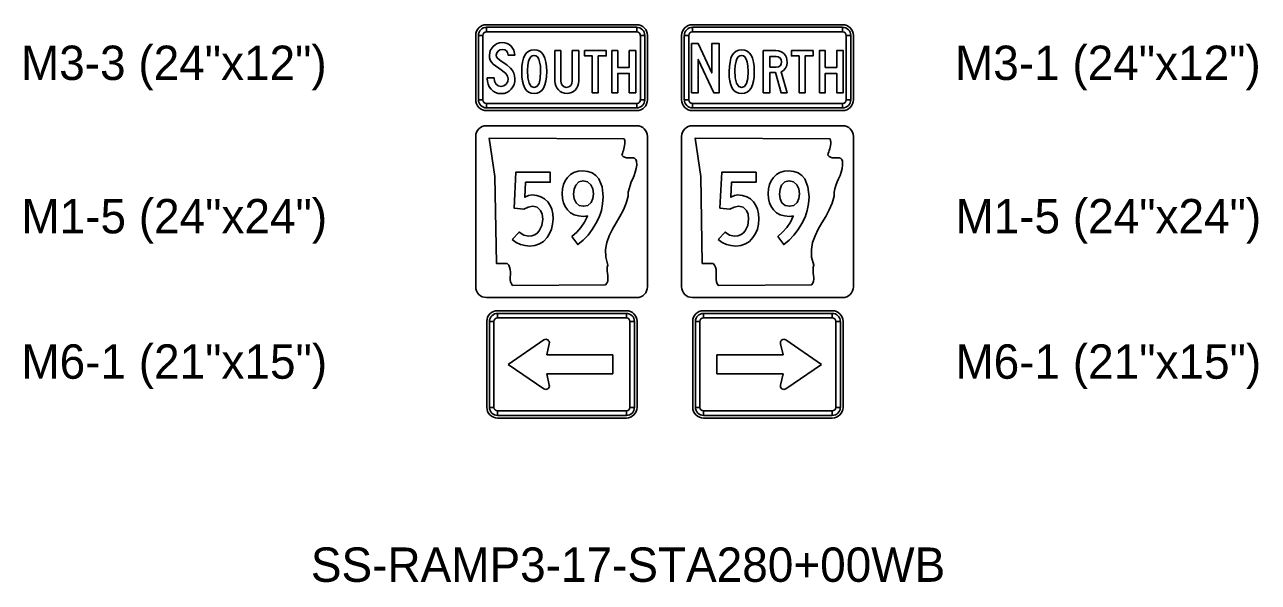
# Model space of a CAD drawing. Extents: x 620856.8 to 620948.6, y 415598.8 to 415658.2.
# Drawn here: x 620932.7 to 620947.07, y 415628.85 to 415635.34 of the extents above; entities that cross this region are included whole.
import ezdxf

# ---------------------------------------------------------------- set-up
doc = ezdxf.new("R2010")
doc.units = 0
doc.layers.add('SIGNS', color=7, linetype='Continuous')

msp = doc.modelspace()

# ---------------------------------------------------------------- linework, layer by layer
at = {"layer": 'SIGNS'}
for p, q in [((620939.83, 415635.34), (620938.08, 415635.34)), ((620938.08, 415635.256), (620938.08, 415635.309)), ((620939.83, 415635.309), (620939.83, 415635.256)), ((620942.228, 415635.34), (620940.478, 415635.34)), ((620940.478, 415635.256), (620940.478, 415635.309)), ((620942.228, 415635.309), (620942.228, 415635.256)), ((620937.955, 415635.215), (620937.955, 415634.465)), ((620937.986, 415635.215), (620938.038, 415635.215)), ((620939.872, 415635.215), (620939.924, 415635.215)), ((620939.955, 415634.465), (620939.955, 415635.215)), ((620940.353, 415635.215), (620940.353, 415634.465)), ((620940.384, 415635.215), (620940.436, 415635.215)), ((620942.27, 415635.215), (620942.322, 415635.215)), ((620942.353, 415634.465), (620942.353, 415635.215)), ((620938.038, 415634.465), (620937.986, 415634.465)), ((620938.08, 415634.371), (620938.08, 415634.423)), ((620939.83, 415634.423), (620939.83, 415634.371)), ((620939.924, 415634.465), (620939.872, 415634.465)), ((620940.436, 415634.465), (620940.384, 415634.465)), ((620940.478, 415634.371), (620940.478, 415634.423)), ((620942.228, 415634.423), (620942.228, 415634.371)), ((620942.322, 415634.465), (620942.27, 415634.465)), ((620938.08, 415634.34), (620939.83, 415634.34)), ((620940.478, 415634.34), (620942.228, 415634.34)), ((620939.83, 415634.164), (620938.08, 415634.164)), ((620942.228, 415634.164), (620940.478, 415634.164)), ((620937.955, 415634.039), (620937.955, 415632.289)), ((620939.955, 415632.289), (620939.955, 415634.039)), ((620940.353, 415634.039), (620940.353, 415632.289)), ((620942.353, 415632.289), (620942.353, 415634.039)), ((620937.955, 415632.289), (620937.955, 415632.289)), ((620940.353, 415632.289), (620940.353, 415632.289)), ((620938.08, 415632.164), (620939.83, 415632.164)), ((620940.478, 415632.164), (620942.228, 415632.164)), ((620938.209, 415632.011), (620939.709, 415632.011)), ((620938.209, 415631.98), (620938.209, 415631.928)), ((620939.709, 415631.928), (620939.709, 415631.98)), ((620942.107, 415632.011), (620940.607, 415632.011)), ((620940.607, 415631.928), (620940.607, 415631.98)), ((620942.107, 415631.98), (620942.107, 415631.928)), ((620938.084, 415630.886), (620938.084, 415631.886)), ((620938.167, 415631.886), (620938.115, 415631.886)), ((620939.803, 415631.886), (620939.751, 415631.886)), ((620939.834, 415631.886), (620939.834, 415630.886)), ((620940.482, 415631.886), (620940.482, 415630.886)), ((620940.513, 415631.886), (620940.565, 415631.886)), ((620942.148, 415631.886), (620942.201, 415631.886)), ((620942.232, 415630.886), (620942.232, 415631.886)), ((620938.334, 415631.386), (620938.749, 415631.672)), ((620938.812, 415631.627), (620938.782, 415631.496)), ((620941.504, 415631.627), (620941.534, 415631.496)), ((620941.982, 415631.386), (620941.567, 415631.672)), ((620938.782, 415631.496), (620939.553, 415631.496)), ((620939.553, 415631.496), (620939.553, 415631.277)), ((620941.534, 415631.496), (620940.763, 415631.496)), ((620940.763, 415631.496), (620940.763, 415631.277)), ((620938.334, 415631.386), (620938.334, 415631.386)), ((620938.749, 415631.101), (620938.334, 415631.386)), ((620939.553, 415631.277), (620938.782, 415631.277)), ((620938.782, 415631.277), (620938.812, 415631.146)), ((620939.553, 415631.277), (620939.553, 415631.277)), ((620940.763, 415631.277), (620940.763, 415631.277)), ((620940.763, 415631.277), (620941.534, 415631.277)), ((620941.534, 415631.277), (620941.504, 415631.146)), ((620941.567, 415631.101), (620941.982, 415631.386)), ((620941.982, 415631.386), (620941.982, 415631.386)), ((620938.115, 415630.886), (620938.167, 415630.886)), ((620938.209, 415630.845), (620938.209, 415630.793)), ((620939.709, 415630.793), (620939.709, 415630.845)), ((620939.751, 415630.886), (620939.803, 415630.886)), ((620940.565, 415630.886), (620940.513, 415630.886)), ((620940.607, 415630.793), (620940.607, 415630.845)), ((620942.107, 415630.845), (620942.107, 415630.793)), ((620942.201, 415630.886), (620942.148, 415630.886)), ((620939.709, 415630.761), (620938.209, 415630.761)), ((620940.607, 415630.761), (620942.107, 415630.761))]:
    msp.add_line(p, q, dxfattribs=at)
for points in [[(620939.83, 415635.309), (620938.08, 415635.309), (620938.08, 415635.256), (620939.83, 415635.256), (620939.83, 415635.309), (620939.83, 415635.309)], [(620942.228, 415635.309), (620940.478, 415635.309), (620940.478, 415635.256), (620942.228, 415635.256), (620942.228, 415635.309), (620942.228, 415635.309)], [(620937.986, 415635.215), (620937.986, 415634.465), (620938.038, 415634.465), (620938.038, 415635.215), (620937.986, 415635.215), (620937.986, 415635.215)], [(620938.089, 415634.72), (620938.089, 415634.715), (620938.091, 415634.68), (620938.099, 415634.648), (620938.113, 415634.618), (620938.133, 415634.591), (620938.158, 415634.567), (620938.186, 415634.55), (620938.216, 415634.54), (620938.251, 415634.537), (620938.285, 415634.54), (620938.316, 415634.55), (620938.343, 415634.566), (620938.368, 415634.589), (620938.387, 415634.616), (620938.401, 415634.645), (620938.409, 415634.677), (620938.412, 415634.712), (620938.408, 415634.745), (620938.399, 415634.776), (620938.383, 415634.806), (620938.36, 415634.834), (620938.317, 415634.871), (620938.251, 415634.917), (620938.207, 415634.95), (620938.197, 415634.967), (620938.194, 415634.986), (620938.199, 415635.011), (620938.215, 415635.033), (620938.237, 415635.047), (620938.263, 415635.052), (620938.292, 415635.048), (620938.312, 415635.034), (620938.324, 415635.015), (620938.332, 415634.986), (620938.412, 415634.986), (620938.399, 415635.044), (620938.368, 415635.09), (620938.346, 415635.108), (620938.321, 415635.121), (620938.292, 415635.129), (620938.261, 415635.131), (620938.232, 415635.129), (620938.205, 415635.12), (620938.18, 415635.107), (620938.158, 415635.087), (620938.125, 415635.039), (620938.115, 415634.984), (620938.117, 415634.955), (620938.125, 415634.928), (620938.139, 415634.904), (620938.158, 415634.882), (620938.251, 415634.816), (620938.286, 415634.789), (620938.307, 415634.77), (620938.326, 415634.741), (620938.333, 415634.711), (620938.327, 415634.677), (620938.311, 415634.648), (620938.284, 415634.627), (620938.251, 415634.62), (620938.215, 415634.628), (620938.188, 415634.651), (620938.172, 415634.683), (620938.168, 415634.72)], [(620939.924, 415634.465), (620939.924, 415635.215), (620939.872, 415635.215), (620939.872, 415634.465), (620939.924, 415634.465), (620939.924, 415634.465)], [(620940.384, 415635.215), (620940.384, 415634.465), (620940.436, 415634.465), (620940.436, 415635.215), (620940.384, 415635.215), (620940.384, 415635.215)], [(620942.322, 415634.465), (620942.322, 415635.215), (620942.27, 415635.215), (620942.27, 415634.465), (620942.322, 415634.465), (620942.322, 415634.465)], [(620938.877, 415635.038), (620938.877, 415634.683), (620938.88, 415634.655), (620938.888, 415634.628), (620938.901, 415634.604), (620938.918, 415634.581), (620938.939, 415634.562), (620938.963, 415634.549), (620938.989, 415634.541), (620939.018, 415634.539), (620939.045, 415634.541), (620939.071, 415634.55), (620939.094, 415634.564), (620939.116, 415634.583), (620939.132, 415634.606), (620939.144, 415634.63), (620939.152, 415634.657), (620939.154, 415634.685), (620939.154, 415635.038), (620939.079, 415635.038), (620939.079, 415634.688), (620939.075, 415634.657), (620939.062, 415634.633), (620939.04, 415634.615), (620939.01, 415634.609), (620938.983, 415634.615), (620938.961, 415634.634), (620938.949, 415634.658), (620938.945, 415634.688), (620938.945, 415635.038)], [(620939.311, 415634.548), (620939.382, 415634.548), (620939.382, 415634.977), (620939.474, 415634.977), (620939.474, 415635.038), (620939.222, 415635.038), (620939.222, 415634.977), (620939.311, 415634.977)], [(620939.541, 415634.548), (620939.609, 415634.548), (620939.609, 415634.773), (620939.743, 415634.773), (620939.743, 415634.548), (620939.818, 415634.548), (620939.818, 415635.038), (620939.743, 415635.038), (620939.743, 415634.842), (620939.609, 415634.842), (620939.609, 415635.038), (620939.541, 415635.038)], [(620940.468, 415634.548), (620940.547, 415634.548), (620940.547, 415634.935), (620940.727, 415634.548), (620940.791, 415634.548), (620940.791, 415635.12), (620940.704, 415635.12), (620940.704, 415634.779), (620940.547, 415635.12), (620940.468, 415635.12)], [(620941.72, 415634.548), (620941.791, 415634.548), (620941.791, 415634.977), (620941.883, 415634.977), (620941.883, 415635.038), (620941.631, 415635.038), (620941.631, 415634.977), (620941.72, 415634.977)], [(620941.958, 415634.548), (620942.025, 415634.548), (620942.025, 415634.773), (620942.159, 415634.773), (620942.159, 415634.548), (620942.234, 415634.548), (620942.234, 415635.038), (620942.159, 415635.038), (620942.159, 415634.842), (620942.025, 415634.842), (620942.025, 415635.038), (620941.958, 415635.038)], [(620938.08, 415634.371), (620939.83, 415634.371), (620939.83, 415634.423), (620938.08, 415634.423), (620938.08, 415634.371), (620938.08, 415634.371)], [(620940.478, 415634.371), (620942.228, 415634.371), (620942.228, 415634.423), (620940.478, 415634.423), (620940.478, 415634.371), (620940.478, 415634.371)], [(620939.685, 415634.01), (620939.69, 415633.991), (620939.691, 415633.971), (620939.691, 415633.952), (620939.688, 415633.933), (620939.684, 415633.914), (620939.679, 415633.895), (620939.674, 415633.876), (620939.668, 415633.858), (620939.663, 415633.839), (620939.658, 415633.821), (620939.672, 415633.805), (620939.689, 415633.796), (620939.709, 415633.792), (620939.73, 415633.791), (620939.752, 415633.792), (620939.772, 415633.792), (620939.791, 415633.79), (620939.808, 415633.784), (620939.821, 415633.772), (620939.829, 415633.752), (620939.83, 415633.706), (620939.824, 415633.664), (620939.813, 415633.623), (620939.799, 415633.585), (620939.783, 415633.546), (620939.767, 415633.509), (620939.752, 415633.47), (620939.74, 415633.43), (620939.732, 415633.389), (620939.73, 415633.345), (620939.708, 415633.263), (620939.674, 415633.185), (620939.633, 415633.109), (620939.589, 415633.034), (620939.546, 415632.959), (620939.508, 415632.883), (620939.48, 415632.805), (620939.466, 415632.722), (620939.469, 415632.635), (620939.495, 415632.541), (620939.487, 415632.518), (620939.485, 415632.494), (620939.485, 415632.47), (620939.488, 415632.446), (620939.492, 415632.422), (620939.494, 415632.399), (620939.495, 415632.376), (620939.492, 415632.354), (620939.483, 415632.333), (620939.468, 415632.313), (620938.384, 415632.303), (620938.37, 415632.323), (620938.361, 415632.347), (620938.357, 415632.373), (620938.357, 415632.401), (620938.358, 415632.431), (620938.358, 415632.461), (620938.356, 415632.49), (620938.35, 415632.516), (620938.339, 415632.541), (620938.321, 415632.561), (620938.195, 415632.561), (620938.177, 415633.573), (620938.113, 415634.02), (620939.685, 415634.01), (620939.685, 415634.01)], [(620942.083, 415634.01), (620942.088, 415633.991), (620942.089, 415633.971), (620942.089, 415633.952), (620942.086, 415633.933), (620942.082, 415633.914), (620942.077, 415633.895), (620942.072, 415633.876), (620942.066, 415633.858), (620942.061, 415633.839), (620942.056, 415633.821), (620942.07, 415633.805), (620942.087, 415633.796), (620942.107, 415633.792), (620942.128, 415633.791), (620942.15, 415633.792), (620942.17, 415633.792), (620942.189, 415633.79), (620942.206, 415633.784), (620942.219, 415633.772), (620942.227, 415633.752), (620942.228, 415633.706), (620942.222, 415633.664), (620942.211, 415633.623), (620942.197, 415633.585), (620942.181, 415633.546), (620942.165, 415633.509), (620942.15, 415633.47), (620942.138, 415633.43), (620942.13, 415633.389), (620942.128, 415633.345), (620942.106, 415633.263), (620942.072, 415633.185), (620942.031, 415633.109), (620941.987, 415633.034), (620941.944, 415632.959), (620941.906, 415632.883), (620941.878, 415632.805), (620941.864, 415632.722), (620941.867, 415632.635), (620941.893, 415632.541), (620941.885, 415632.518), (620941.883, 415632.494), (620941.883, 415632.47), (620941.886, 415632.446), (620941.89, 415632.422), (620941.892, 415632.399), (620941.893, 415632.376), (620941.89, 415632.354), (620941.881, 415632.333), (620941.866, 415632.313), (620940.782, 415632.303), (620940.768, 415632.323), (620940.759, 415632.347), (620940.755, 415632.373), (620940.755, 415632.401), (620940.756, 415632.431), (620940.756, 415632.461), (620940.754, 415632.49), (620940.748, 415632.516), (620940.737, 415632.541), (620940.719, 415632.561), (620940.593, 415632.561), (620940.575, 415633.573), (620940.511, 415634.02), (620942.083, 415634.01), (620942.083, 415634.01)], [(620938.38, 415632.838), (620938.427, 415632.805), (620938.477, 415632.782), (620938.53, 415632.768), (620938.584, 415632.763), (620938.644, 415632.769), (620938.697, 415632.788), (620938.744, 415632.818), (620938.785, 415632.861), (620938.815, 415632.909), (620938.837, 415632.961), (620938.85, 415633.019), (620938.855, 415633.082), (620938.851, 415633.139), (620938.84, 415633.191), (620938.82, 415633.237), (620938.793, 415633.278), (620938.757, 415633.312), (620938.714, 415633.337), (620938.665, 415633.352), (620938.611, 415633.358), (620938.569, 415633.351), (620938.526, 415633.331), (620938.535, 415633.506), (620938.822, 415633.506), (620938.822, 415633.622), (620938.421, 415633.622), (620938.401, 415633.206), (620938.517, 415633.191), (620938.566, 415633.217), (620938.619, 415633.226), (620938.671, 415633.214), (620938.709, 415633.179), (620938.729, 415633.133), (620938.735, 415633.076), (620938.725, 415633.001), (620938.695, 415632.94), (620938.671, 415632.913), (620938.642, 415632.894), (620938.609, 415632.882), (620938.572, 415632.879), (620938.514, 415632.891), (620938.46, 415632.926)], [(620940.778, 415632.838), (620940.825, 415632.805), (620940.875, 415632.782), (620940.928, 415632.768), (620940.982, 415632.763), (620941.042, 415632.769), (620941.095, 415632.788), (620941.142, 415632.818), (620941.183, 415632.861), (620941.213, 415632.909), (620941.235, 415632.961), (620941.248, 415633.019), (620941.253, 415633.082), (620941.249, 415633.139), (620941.238, 415633.191), (620941.218, 415633.237), (620941.191, 415633.278), (620941.155, 415633.312), (620941.112, 415633.337), (620941.063, 415633.352), (620941.009, 415633.358), (620940.967, 415633.351), (620940.924, 415633.331), (620940.933, 415633.506), (620941.22, 415633.506), (620941.22, 415633.622), (620940.819, 415633.622), (620940.799, 415633.206), (620940.915, 415633.191), (620940.964, 415633.217), (620941.017, 415633.226), (620941.069, 415633.214), (620941.107, 415633.179), (620941.127, 415633.133), (620941.133, 415633.076), (620941.123, 415633.001), (620941.093, 415632.94), (620941.069, 415632.913), (620941.04, 415632.894), (620941.007, 415632.882), (620940.97, 415632.879), (620940.912, 415632.891), (620940.858, 415632.926)], [(620938.209, 415631.98), (620939.709, 415631.98), (620939.709, 415631.928), (620938.209, 415631.928), (620938.209, 415631.98), (620938.209, 415631.98)], [(620942.107, 415631.98), (620940.607, 415631.98), (620940.607, 415631.928), (620942.107, 415631.928), (620942.107, 415631.98), (620942.107, 415631.98)], [(620938.115, 415630.886), (620938.115, 415631.886), (620938.167, 415631.886), (620938.167, 415630.886), (620938.115, 415630.886), (620938.115, 415630.886)], [(620939.803, 415631.886), (620939.803, 415630.886), (620939.751, 415630.886), (620939.751, 415631.886), (620939.803, 415631.886), (620939.803, 415631.886)], [(620940.513, 415631.886), (620940.513, 415630.886), (620940.565, 415630.886), (620940.565, 415631.886), (620940.513, 415631.886), (620940.513, 415631.886)], [(620942.201, 415630.886), (620942.201, 415631.886), (620942.148, 415631.886), (620942.148, 415630.886), (620942.201, 415630.886), (620942.201, 415630.886)], [(620939.709, 415630.793), (620938.209, 415630.793), (620938.209, 415630.845), (620939.709, 415630.845), (620939.709, 415630.793), (620939.709, 415630.793)], [(620940.607, 415630.793), (620942.107, 415630.793), (620942.107, 415630.845), (620940.607, 415630.845), (620940.607, 415630.793), (620940.607, 415630.793)]]:
    msp.add_lwpolyline(points, close=True, dxfattribs=at)
for points in [[(620938.782, 415634.794), (620938.779, 415634.853), (620938.773, 415634.905), (620938.761, 415634.949), (620938.746, 415634.985), (620938.725, 415635.012), (620938.7, 415635.032), (620938.671, 415635.044), (620938.637, 415635.048), (620938.602, 415635.044), (620938.573, 415635.032), (620938.547, 415635.012), (620938.527, 415634.985), (620938.511, 415634.949), (620938.499, 415634.905), (620938.492, 415634.853), (620938.49, 415634.794), (620938.492, 415634.734), (620938.499, 415634.682), (620938.51, 415634.638), (620938.526, 415634.602), (620938.546, 415634.574), (620938.571, 415634.554), (620938.6, 415634.542), (620938.634, 415634.539), (620938.669, 415634.542), (620938.699, 415634.554), (620938.724, 415634.574), (620938.745, 415634.602), (620938.761, 415634.638), (620938.772, 415634.682), (620938.779, 415634.734), (620938.782, 415634.794)], [(620938.711, 415634.796), (620938.706, 415634.715), (620938.692, 415634.656), (620938.668, 415634.621), (620938.635, 415634.61), (620938.601, 415634.622), (620938.577, 415634.659), (620938.562, 415634.721), (620938.557, 415634.809), (620938.56, 415634.866), (620938.57, 415634.915), (620938.581, 415634.944), (620938.595, 415634.965), (620938.613, 415634.978), (620938.635, 415634.982), (620938.656, 415634.978), (620938.674, 415634.964), (620938.688, 415634.94), (620938.699, 415634.908), (620938.708, 415634.857), (620938.711, 415634.796)], [(620941.198, 415634.794), (620941.196, 415634.853), (620941.189, 415634.905), (620941.178, 415634.949), (620941.162, 415634.985), (620941.141, 415635.012), (620941.117, 415635.032), (620941.087, 415635.044), (620941.053, 415635.048), (620941.019, 415635.044), (620940.989, 415635.032), (620940.964, 415635.012), (620940.943, 415634.985), (620940.927, 415634.949), (620940.916, 415634.905), (620940.909, 415634.853), (620940.906, 415634.794), (620940.908, 415634.734), (620940.915, 415634.682), (620940.926, 415634.638), (620940.942, 415634.602), (620940.962, 415634.574), (620940.987, 415634.554), (620941.017, 415634.542), (620941.05, 415634.539), (620941.085, 415634.542), (620941.115, 415634.554), (620941.14, 415634.574), (620941.161, 415634.602), (620941.177, 415634.638), (620941.189, 415634.682), (620941.196, 415634.734), (620941.198, 415634.794)], [(620941.128, 415634.796), (620941.123, 415634.715), (620941.108, 415634.656), (620941.084, 415634.621), (620941.051, 415634.61), (620941.017, 415634.622), (620940.993, 415634.659), (620940.978, 415634.721), (620940.974, 415634.809), (620940.977, 415634.866), (620940.986, 415634.915), (620940.997, 415634.944), (620941.012, 415634.965), (620941.03, 415634.978), (620941.051, 415634.982), (620941.072, 415634.978), (620941.09, 415634.964), (620941.105, 415634.94), (620941.116, 415634.908), (620941.125, 415634.857), (620941.128, 415634.796)], [(620941.304, 415634.548), (620941.381, 415634.548), (620941.381, 415634.782), (620941.447, 415634.782), (620941.511, 415634.548), (620941.581, 415634.548), (620941.51, 415634.79), (620941.54, 415634.807), (620941.563, 415634.834), (620941.577, 415634.865), (620941.581, 415634.901), (620941.579, 415634.931), (620941.573, 415634.957), (620941.562, 415634.98), (620941.548, 415635), (620941.529, 415635.017), (620941.506, 415635.029), (620941.48, 415635.036), (620941.451, 415635.038), (620941.304, 415635.038), (620941.304, 415634.548)], [(620941.381, 415634.846), (620941.381, 415634.971), (620941.453, 415634.971), (620941.478, 415634.967), (620941.498, 415634.954), (620941.511, 415634.934), (620941.516, 415634.908), (620941.512, 415634.881), (620941.501, 415634.862), (620941.482, 415634.85), (620941.455, 415634.846), (620941.381, 415634.846)], [(620938.08, 415634.164), (620938.08, 415634.164)], [(620939.83, 415634.164), (620939.83, 415634.164)], [(620940.478, 415634.164), (620940.478, 415634.164)], [(620942.228, 415634.164), (620942.228, 415634.164)], [(620937.955, 415634.039), (620937.955, 415634.039)], [(620940.353, 415634.039), (620940.353, 415634.039)], [(620939.075, 415632.875), (620939.144, 415632.78), (620939.207, 415632.833), (620939.263, 415632.891), (620939.312, 415632.955), (620939.355, 415633.025), (620939.392, 415633.101), (620939.418, 415633.178), (620939.433, 415633.256), (620939.439, 415633.335), (620939.426, 415633.454), (620939.389, 415633.545), (620939.354, 415633.586), (620939.311, 415633.615), (620939.26, 415633.632), (620939.201, 415633.638), (620939.147, 415633.633), (620939.099, 415633.619), (620939.058, 415633.595), (620939.023, 415633.561), (620938.997, 415633.522), (620938.978, 415633.478), (620938.967, 415633.429), (620938.963, 415633.375), (620938.967, 415633.317), (620938.979, 415633.266), (620938.997, 415633.222), (620939.025, 415633.184), (620939.06, 415633.151), (620939.103, 415633.128), (620939.153, 415633.114), (620939.21, 415633.109), (620939.234, 415633.111), (620939.257, 415633.113), (620939.255, 415633.113), (620939.221, 415633.043), (620939.18, 415632.981), (620939.131, 415632.925), (620939.075, 415632.875)], [(620941.473, 415632.875), (620941.542, 415632.78), (620941.605, 415632.833), (620941.661, 415632.891), (620941.71, 415632.955), (620941.753, 415633.025), (620941.79, 415633.101), (620941.816, 415633.178), (620941.831, 415633.256), (620941.837, 415633.335), (620941.824, 415633.454), (620941.787, 415633.545), (620941.752, 415633.586), (620941.709, 415633.615), (620941.658, 415633.632), (620941.599, 415633.638), (620941.545, 415633.633), (620941.497, 415633.619), (620941.456, 415633.595), (620941.421, 415633.561), (620941.395, 415633.522), (620941.376, 415633.478), (620941.365, 415633.429), (620941.361, 415633.375), (620941.365, 415633.317), (620941.377, 415633.266), (620941.395, 415633.222), (620941.423, 415633.184), (620941.458, 415633.151), (620941.501, 415633.128), (620941.551, 415633.114), (620941.608, 415633.109), (620941.632, 415633.111), (620941.655, 415633.113), (620941.653, 415633.113), (620941.619, 415633.043), (620941.578, 415632.981), (620941.529, 415632.925), (620941.473, 415632.875)], [(620939.326, 415633.371), (620939.32, 415633.315), (620939.299, 415633.27), (620939.261, 415633.237), (620939.21, 415633.226), (620939.16, 415633.236), (620939.123, 415633.268), (620939.102, 415633.312), (620939.095, 415633.367), (620939.101, 415633.425), (620939.119, 415633.472), (620939.155, 415633.51), (620939.206, 415633.523), (620939.257, 415633.511), (620939.297, 415633.475), (620939.319, 415633.428), (620939.326, 415633.371)], [(620941.724, 415633.371), (620941.718, 415633.315), (620941.697, 415633.27), (620941.659, 415633.237), (620941.608, 415633.226), (620941.558, 415633.236), (620941.521, 415633.268), (620941.5, 415633.312), (620941.493, 415633.367), (620941.499, 415633.425), (620941.517, 415633.472), (620941.553, 415633.51), (620941.604, 415633.523), (620941.655, 415633.511), (620941.695, 415633.475), (620941.717, 415633.428), (620941.724, 415633.371)], [(620938.08, 415632.164), (620938.08, 415632.164)], [(620939.83, 415632.164), (620939.83, 415632.164)], [(620940.478, 415632.164), (620940.478, 415632.164)], [(620942.228, 415632.164), (620942.228, 415632.164)]]:
    msp.add_lwpolyline(points, dxfattribs=at)
for centre, radius, start, end in [((620938.08, 415635.215), 0.125, 90.0002, 179.9998), ((620938.08, 415635.215), 0.0937, 90.0002, 179.9998), ((620939.83, 415635.215), 0.125, 360, 90.0002), ((620939.83, 415635.215), 0.0937, 360, 90.0002), ((620940.478, 415635.215), 0.125, 90.0002, 179.9998), ((620940.478, 415635.215), 0.0937, 90.0002, 179.9998), ((620942.228, 415635.215), 0.125, 360, 90.0002), ((620942.228, 415635.215), 0.0937, 360, 90.0002), ((620938.08, 415635.215), 0.0417, 90.0002, 179.9998), ((620939.83, 415635.215), 0.0417, 360, 90.0002), ((620940.478, 415635.215), 0.0417, 90.0002, 179.9998), ((620942.228, 415635.215), 0.0417, 360, 90.0002), ((620938.08, 415634.465), 0.125, 179.9998, 270.0001), ((620938.08, 415634.465), 0.0937, 179.9998, 270.0001), ((620938.08, 415634.465), 0.0417, 179.9998, 270.0001), ((620939.83, 415634.465), 0.125, 270.0001, 0.0003), ((620939.83, 415634.465), 0.0937, 270.0001, 0.0003), ((620939.83, 415634.465), 0.0417, 270.0001, 0.0003), ((620940.478, 415634.465), 0.125, 179.9998, 270.0001), ((620940.478, 415634.465), 0.0937, 179.9998, 270.0001), ((620940.478, 415634.465), 0.0417, 179.9998, 270.0001), ((620942.228, 415634.465), 0.125, 270.0001, 0.0003), ((620942.228, 415634.465), 0.0937, 270.0001, 0.0003), ((620942.228, 415634.465), 0.0417, 270.0001, 0.0003), ((620938.08, 415634.039), 0.125, 90.0002, 179.9998), ((620939.83, 415634.039), 0.125, 360, 90), ((620940.478, 415634.039), 0.125, 90.0002, 179.9998), ((620942.228, 415634.039), 0.125, 360, 90), ((620938.08, 415632.289), 0.125, 180, 270), ((620939.83, 415632.289), 0.125, 270.0001, 0.0003), ((620940.478, 415632.289), 0.125, 180, 270), ((620942.228, 415632.289), 0.125, 270.0001, 0.0003), ((620938.209, 415631.886), 0.125, 89.9998, 180), ((620938.209, 415631.886), 0.0937, 89.9998, 180), ((620939.709, 415631.886), 0.125, 0.0002, 89.9998), ((620939.709, 415631.886), 0.0937, 0.0002, 89.9998), ((620940.607, 415631.886), 0.125, 90.0002, 179.9998), ((620940.607, 415631.886), 0.0937, 90.0002, 179.9998), ((620942.107, 415631.886), 0.125, 360, 90.0002), ((620942.107, 415631.886), 0.0937, 360, 90.0002), ((620938.209, 415631.886), 0.0417, 89.9998, 180), ((620939.709, 415631.886), 0.0417, 0.0002, 89.9998), ((620940.607, 415631.886), 0.0417, 90.0002, 179.9998), ((620942.107, 415631.886), 0.0417, 360, 90.0002), ((620938.771, 415631.636), 0.0417, 347.0496, 122.2756), ((620941.544, 415631.636), 0.0417, 57.7244, 192.9504), ((620938.771, 415631.136), 0.0417, 237.7241, 12.9501), ((620941.544, 415631.136), 0.0417, 167.0499, 302.2759), ((620938.209, 415630.886), 0.125, 179.9997, 269.9999), ((620938.209, 415630.886), 0.0937, 179.9997, 269.9999), ((620938.209, 415630.886), 0.0417, 179.9997, 269.9999), ((620939.709, 415630.886), 0.0937, 269.9999, 0.0002), ((620939.709, 415630.886), 0.0417, 269.9999, 0.0002), ((620939.709, 415630.886), 0.125, 269.9999, 0.0002), ((620940.607, 415630.886), 0.125, 179.9998, 270.0001), ((620940.607, 415630.886), 0.0937, 179.9998, 270.0001), ((620940.607, 415630.886), 0.0417, 179.9998, 270.0001), ((620942.107, 415630.886), 0.0937, 270.0001, 0.0003), ((620942.107, 415630.886), 0.0417, 270.0001, 0.0003), ((620942.107, 415630.886), 0.125, 270.0001, 0.0003)]:
    msp.add_arc(centre, radius, start, end, dxfattribs=at)

# ---------------------------------------------------------------- texts
for s, p in [('M3-3 (24"x12")', (620932.659, 415634.696)), ('M3-1 (24"x12")', (620943.536, 415634.696)), ('M1-5 (24"x24")', (620932.664, 415632.911)), ('M1-5 (24"x24")', (620943.541, 415632.911)), ('M6-1 (21"x15")', (620932.664, 415631.219)), ('M6-1 (21"x15")', (620943.541, 415631.219)), ('SS-RAMP3-17-STA280+00WB', (620936.035, 415628.855))]:
    msp.add_text(s, height=0.4, rotation=0, dxfattribs=at).set_placement(p)

doc.saveas('drawing.dxf')
